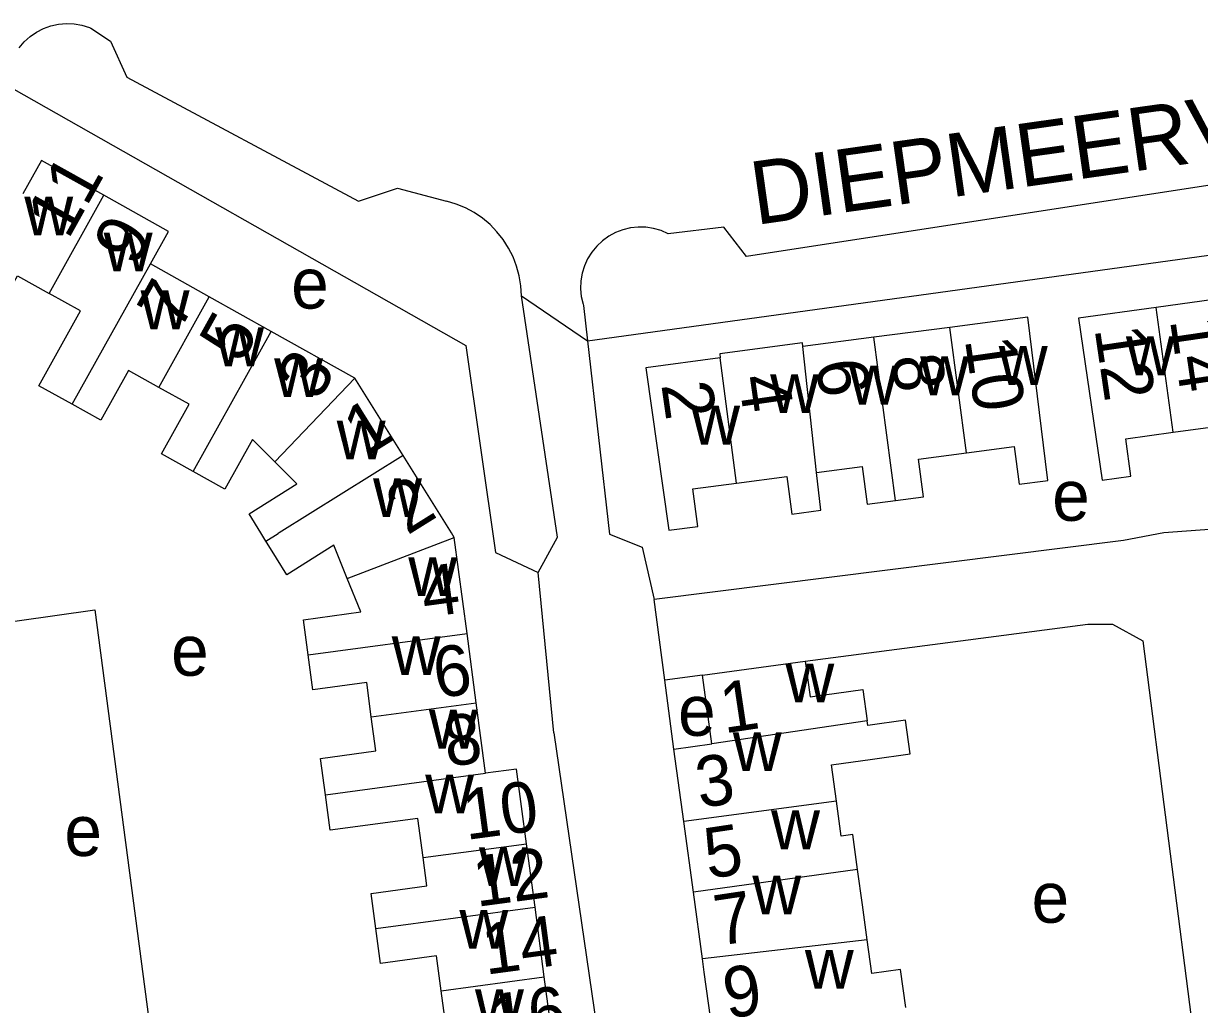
# Model space of a CAD drawing. Extents: x 162667 to 164645, y 379003 to 382150.
# Drawn here: x 163419.1 to 163512.2, y 381462.7 to 381540.3 of the extents above; entities that cross this region are included whole.
import ezdxf

# ---------------------------------------------------------------- set-up
doc = ezdxf.new("R2010")
doc.units = 0
for name, color, linetype in [('BLT_Basislijn', 7, 'Continuous'), ('BLT_Bebouwing', 7, 'Continuous'), ('BLT_Centroide', 7, 'Continuous'), ('BLT_Huisnummer', 7, 'Continuous'), ('BLT_Huisnummer_ tussenligend', 7, 'Continuous'), ('BLT_Onderverdeling_panden', 7, 'Continuous'), ('BLT_Straatnaam', 7, 'Continuous'), ('BLT_Vlakafsluiter', 7, 'Continuous')]:
    doc.layers.add(name, color=color, linetype=linetype)

msp = doc.modelspace()

# ---------------------------------------------------------------- linework, layer by layer
at = {"layer": 'BLT_Basislijn'}
for p, q in [((163417.395, 381535.67), (163454.144, 381514.826)), ((163463.765, 381515.19), (163537.608, 381525.381)), ((163463.446, 381517.986), (163463.765, 381515.19)), ((163461.096, 381484.176), (163459.862, 381496.866)), ((163469.885, 381488.351), (163469.043, 381494.727)), ((163472.865, 381488.737), (163469.885, 381488.351)), ((163470.607, 381482.885), (163469.885, 381488.351))]:
    msp.add_line(p, q, dxfattribs=at)
for points in [[(163418.796, 381538.386), (163419.201, 381538.856), (163419.662, 381539.27), (163420.173, 381539.621), (163420.725, 381539.904), (163421.309, 381540.113), (163421.915, 381540.245), (163422.533, 381540.298), (163423.152, 381540.272), (163423.763, 381540.166), (163424.356, 381539.982), (163424.474, 381539.935)], [(163424.474, 381539.935), (163426.023, 381538.902), (163427.313, 381536.062), (163445.638, 381526.25), (163448.735, 381527.282), (163452.606, 381526.25)], [(163531.324, 381530.639), (163525.904, 381530.381), (163524.355, 381528.057), (163516.613, 381528.057), (163476.35, 381521.86), (163474.544, 381524.184), (163470.156, 381523.667)], [(163458.542, 381518.761), (163458.493, 381519.549), (163458.365, 381520.329), (163458.158, 381521.091), (163457.876, 381521.829), (163457.52, 381522.534), (163457.095, 381523.2), (163456.605, 381523.819), (163456.054, 381524.386), (163455.45, 381524.894), (163454.797, 381525.339), (163454.102, 381525.715), (163453.373, 381526.019), (163452.606, 381526.25)], [(163470.156, 381523.667), (163469.591, 381523.914), (163468.999, 381524.086), (163468.39, 381524.18), (163467.774, 381524.195), (163467.161, 381524.129), (163466.562, 381523.985), (163465.986, 381523.764), (163465.444, 381523.471), (163464.944, 381523.11), (163464.495, 381522.688), (163464.105, 381522.211), (163463.779, 381521.687), (163463.524, 381521.126), (163463.344, 381520.537), (163463.242, 381519.929), (163463.219, 381519.313), (163463.276, 381518.699), (163463.411, 381518.098), (163463.446, 381517.986)], [(163459.862, 381496.866), (163461.381, 381499.653), (163458.542, 381518.761)], [(163454.144, 381514.826), (163456.476, 381498.453), (163459.862, 381496.866)], [(163463.765, 381515.19), (163465.511, 381499.911), (163468.091, 381498.878), (163469.043, 381494.727)], [(163514.049, 381500.356), (163509.363, 381500), (163506.175, 381499.41), (163469.043, 381494.727)], [(163406.515, 381491.329), (163424.778, 381493.904), (163430.724, 381448.9)], [(163480.992, 381489.857), (163503.369, 381492.784), (163505.322, 381492.784), (163507.707, 381491.464), (163511.785, 381459.823)], [(163461.096, 381484.176), (163464.682, 381459.551), (163463.131, 381458.992)]]:
    msp.add_lwpolyline(points, dxfattribs=at)
at = {"layer": 'BLT_Bebouwing'}
for p, q in [((163430.618, 381523.852), (163425.485, 381526.713)), ((163429.18, 381521.273), (163430.618, 381523.852)), ((163433.835, 381518.678), (163429.18, 381521.273)), ((163438.747, 381515.94), (163433.835, 381518.678)), ((163514.702, 381518.656), (163508.755, 381517.836)), ((163445.366, 381512.25), (163438.747, 381515.94)), ((163486.432, 381515.471), (163480.809, 381514.736)), ((163492.442, 381516.258), (163486.432, 381515.471)), ((163449.185, 381506.125), (163445.366, 381512.25)), ((163454.232, 381492.041), (163453.222, 381499.632)), ((163454.96, 381486.563), (163454.232, 381492.041)), ((163472.865, 381488.737), (163480.992, 381489.857)), ((163473.614, 381483.3), (163472.865, 381488.737)), ((163455.702, 381480.988), (163454.96, 381486.563)), ((163470.607, 381482.885), (163473.614, 381483.3)), ((163471.384, 381477.168), (163470.607, 381482.885)), ((163458.161, 381481.315), (163455.702, 381480.988)), ((163458.946, 381475.41), (163458.161, 381481.315)), ((163472.146, 381471.568), (163471.384, 381477.168)), ((163459.613, 381470.4), (163458.946, 381475.41)), ((163472.862, 381466.297), (163472.146, 381471.568)), ((163460.348, 381464.873), (163459.613, 381470.4)), ((163461.16, 381458.765), (163460.348, 381464.873))]:
    msp.add_line(p, q, dxfattribs=at)
for points in [[(163425.485, 381526.713), (163420.55, 381529.464), (163419.083, 381526.833)], [(163412.916, 381515.77), (163414.86, 381514.686), (163415.352, 381514.411), (163418.659, 381520.343), (163421.156, 381518.95)], [(163422.993, 381510.173), (163420.356, 381511.643), (163423.654, 381517.558), (163421.156, 381518.95)], [(163508.755, 381517.836), (163502.623, 381516.992), (163504.497, 381504.177), (163506.768, 381504.489), (163506.362, 381507.45), (163510.113, 381507.966)], [(163493.747, 381506.327), (163497.524, 381506.824), (163497.915, 381503.845), (163500, 381504.119), (163500.198, 381504.145), (163500, 381505.65), (163498.608, 381517.064), (163492.442, 381516.258)], [(163480.809, 381514.736), (163480.767, 381515.043), (163474.226, 381514.154), (163474.267, 381513.847)], [(163474.267, 381513.847), (163468.376, 381513.061), (163470.206, 381500.205), (163472.489, 381500.505), (163472.096, 381503.483), (163475.569, 381503.94)], [(163429.838, 381511.508), (163427.438, 381512.846), (163425.248, 381508.916), (163422.993, 381510.173)], [(163432.562, 381504.847), (163430.051, 381506.247), (163432.238, 381510.17), (163429.838, 381511.508)], [(163510.113, 381507.966), (163513.864, 381508.482), (163514.247, 381505.502), (163516.472, 381505.808)], [(163439.018, 381505.63), (163437.266, 381507.382), (163435.073, 381503.447), (163432.562, 381504.847)], [(163453.222, 381499.632), (163453.005, 381500), (163449.185, 381506.125)], [(163488.129, 381502.559), (163490.362, 381502.853), (163489.97, 381505.831), (163493.747, 381506.327)], [(163438.318, 381499.348), (163437.917, 381500), (163436.984, 381501.518), (163440.771, 381503.879), (163439.018, 381505.63)], [(163481.901, 381504.771), (163485.504, 381505.245), (163485.897, 381502.266), (163488.129, 381502.559)], [(163475.569, 381503.94), (163479.541, 381504.462), (163479.932, 381501.483), (163482.225, 381501.784), (163481.901, 381504.771)], [(163444.761, 381496.388), (163443.697, 381499.018), (163439.967, 381496.692), (163439.153, 381497.997), (163438.425, 381499.173), (163438.318, 381499.348)], [(163441.655, 381490.351), (163441.283, 381493.124), (163445.825, 381493.758), (163444.761, 381496.388)], [(163446.657, 381485.448), (163446.294, 381488.152), (163442.028, 381487.579), (163441.655, 381490.351)], [(163480.992, 381489.857), (163481.38, 381487.041), (163485.565, 381487.618), (163485.907, 381485.141)], [(163443.025, 381479.283), (163442.639, 381482.156), (163447.02, 381482.745), (163446.657, 381485.448)], [(163483.46, 381478.774), (163483.064, 381481.646), (163486.326, 381482.096), (163489.298, 381482.506), (163488.93, 381485.179), (163485.958, 381484.769), (163485.907, 381485.141)], [(163450.757, 381474.312), (163450.343, 381477.399), (163443.404, 381476.467), (163443.025, 381479.283)], [(163485.134, 381473.357), (163484.751, 381476.14), (163483.84, 381476.014), (163483.46, 381478.774)], [(163447.008, 381468.707), (163446.636, 381471.477), (163451.058, 381472.071), (163450.757, 381474.312)], [(163485.898, 381467.811), (163485.518, 381470.575), (163485.134, 381473.357)], [(163452.196, 381463.777), (163451.826, 381466.534), (163447.38, 381465.937), (163447.008, 381468.707)], [(163488.948, 381462.452), (163488.535, 381465.452), (163486.265, 381465.139), (163485.898, 381467.811)], [(163476.541, 381460.744), (163473.68, 381460.35), (163473.007, 381465.233), (163472.862, 381466.297)], [(163446.127, 381456.747), (163445.674, 381460.121), (163448.878, 381460.552), (163452.562, 381461.048), (163452.196, 381463.777)]]:
    msp.add_lwpolyline(points, dxfattribs=at)
at = {"layer": 'BLT_Onderverdeling_panden'}
for p, q in [((163421.156, 381518.95), (163425.485, 381526.713)), ((163422.993, 381510.173), (163429.18, 381521.273)), ((163429.838, 381511.508), (163433.835, 381518.678)), ((163510.113, 381507.966), (163508.755, 381517.836)), ((163432.562, 381504.847), (163438.747, 381515.94)), ((163488.129, 381502.559), (163486.432, 381515.471)), ((163493.747, 381506.327), (163492.442, 381516.258)), ((163481.901, 381504.771), (163480.809, 381514.736)), ((163475.569, 381503.94), (163474.267, 381513.847)), ((163439.018, 381505.63), (163445.366, 381512.25)), ((163449.185, 381506.125), (163439.363, 381500)), ((163438.318, 381499.348), (163439.278, 381499.947)), ((163439.363, 381500), (163439.278, 381499.947)), ((163444.761, 381496.388), (163453.222, 381499.632)), ((163441.655, 381490.351), (163454.232, 381492.041)), ((163446.657, 381485.448), (163454.96, 381486.563)), ((163485.907, 381485.141), (163473.614, 381483.3)), ((163443.025, 381479.283), (163455.702, 381480.988)), ((163483.46, 381478.774), (163471.384, 381477.168)), ((163450.757, 381474.312), (163458.946, 381475.41)), ((163485.134, 381473.357), (163472.146, 381471.568)), ((163447.008, 381468.707), (163459.613, 381470.4)), ((163485.898, 381467.811), (163472.862, 381466.297)), ((163452.196, 381463.777), (163460.348, 381464.873))]:
    msp.add_line(p, q, dxfattribs=at)
at = {"layer": 'BLT_Vlakafsluiter'}
msp.add_line((163458.542, 381518.761), (163463.765, 381515.19), dxfattribs=at)

# ---------------------------------------------------------------- texts
at = {"layer": 'BLT_Centroide'}
for s, p in [('w', (163419.203, 381523.531)), ('w', (163425.484, 381520.688)), ('e', (163440.32, 381517.746)), ('w', (163428.406, 381516.109)), ('w', (163434.297, 381513.188)), ('w', (163506.375, 381512.469)), ('w', (163496.312, 381511.703)), ('w', (163438.969, 381510.75)), ('w', (163490.094, 381510.891)), ('w', (163484.469, 381510.156)), ('w', (163478.219, 381509.484)), ('w', (163471.969, 381506.984)), ('w', (163443.922, 381505.812)), ('w', (163446.797, 381501.25)), ('e', (163500.539, 381500.956)), ('w', (163449.586, 381495)), ('e', (163430.819, 381488.698)), ('w', (163448.273, 381488.75)), ('w', (163479.43, 381486.594)), ('e', (163470.934, 381483.945)), ('w', (163451.219, 381482.938)), ('w', (163475.266, 381481.156)), ('w', (163450.922, 381477.812)), ('e', (163422.374, 381474.438)), ('w', (163478.297, 381474.969)), ('w', (163455.18, 381472.062)), ('w', (163476.812, 381469.812)), ('e', (163498.908, 381469.157)), ('w', (163453.633, 381467.094)), ('w', (163480.969, 381463.938)), ('w', (163454.867, 381460.812))]:
    msp.add_text(s, height=4, dxfattribs=at).set_placement(p)
at = {"layer": 'BLT_Huisnummer'}
for s, height, rotation, p in [('11', 4, 60.86526, (163422.669, 381523.136)), ('9', 4, 60.86526, (163427.97, 381520.956)), ('7', 4, 60.85776, (163431.461, 381515.865)), ('5', 4, 60.85776, (163436.352, 381513.298)), ('12', 3.9999, 278.31967, (163503.884, 381516.145)), ('10', 4, 278.1014, (163493.623, 381515.296)), ('6', 4, 278.1014, (163481.821, 381513.503)), ('2', 4, 278.1014, (163469.602, 381511.736)), ('1', 4, 31.94767, (163446.136, 381505.916)), ('2', 4, 31.94767, (163449.499, 381499.776)), ('6', 4, 7.64843, (163451.837, 381486.913)), ('1', 4, 8.51732, (163474.583, 381484.128)), ('10', 4, 7.6368, (163454.167, 381475.699)), ('5', 4, 8.51732, (163473.306, 381472.622)), ('14', 4, 7.6368, (163455.709, 381465.034)), ('9', 4, 8.51732, (163474.822, 381461.558))]:
    msp.add_text(s, height=height, rotation=rotation, dxfattribs=at).set_placement(p)
at = {"layer": 'BLT_Huisnummer_ tussenligend'}
for s, height, rotation, p in [('14', 3.9999, 278.31967, (163509.85, 381516.84)), ('3', 4, 60.85776, (163442.456, 381510.31)), ('8', 4, 278.1014, (163487.791, 381513.902)), ('4', 4, 278.1014, (163475.704, 381512.293)), ('4', 4, 7.64843, (163450.888, 381493.293)), ('8', 4, 7.64843, (163452.659, 381481.484)), ('3', 4, 8.51732, (163472.647, 381478.224)), ('12', 4, 7.6368, (163454.996, 381470.407)), ('7', 4, 8.51732, (163474.106, 381467.325)), ('16', 4, 7.6368, (163456.389, 381459.468))]:
    msp.add_text(s, height=height, rotation=rotation, dxfattribs=at).set_placement(p)
at = {"layer": 'BLT_Straatnaam'}
msp.add_text('DIEPMEERVEN', height=5, rotation=8.05193, dxfattribs=at).set_placement((163477.07, 381524.353))

doc.saveas('drawing.dxf')
